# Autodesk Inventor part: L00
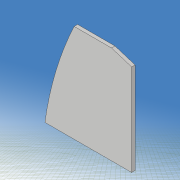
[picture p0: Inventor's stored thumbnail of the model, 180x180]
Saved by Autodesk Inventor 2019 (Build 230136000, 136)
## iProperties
Created: 2021-05
Part Number: L00
Material: 一般
Document SubType Name: Modeling
Designer: kikut
Density: 1 g/cm^3
Appearance: 既定
Mass: 0.00934248 g
Surface Area: 0.426451 cm^2
Volume: 0.00934248 cm^3
Author: kikut
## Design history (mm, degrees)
sketch "スケッチ1"
  geometry: L1 (80, 60)-(-80, 60); L2 (-80, 60)-(-80, -60); L3 (-80, -60)-(80, -60); L4 (80, -60)-(80, 60); L5 (80, 60)-(-80, -60); L6 (-80, 60)-(80, -60); 1 further point
  constraints: 12 end point, 2 midpoint, 2 parallel, 1 horizontal, 1 perpendicular
  dimensions: "d0" = 160 distance of L2.end L3.end; "d1" = 120 distance of L1.end L2.end
extrude "押し出し1" new body sketch "スケッチ1" stored distance "d2" = 0.6; taper "d3" = 0 deg
sketch "スケッチ2"
  geometry: L1 (-140, 0)-(140, 0) reference; L2 (0, -54)-(20, -30); L3 (0, 54)-(20, 30); L4 (0, -3)-(6.514, -3); L5 (6.514, -3)-(16, -6); L6 (16, -6)-(24, -3); L7 (24, -3)-(33.716, -3); L8 (0, 3)-(6.514, 3); L9 (6.514, 3)-(16, 6); L10 (16, 6)-(24, 3); L11 (24, 3)-(33.716, 3); L12 (0, -98)-(0, 98) reference; L13 (-100, -70)-(100, -70); L14 (100, -70)-(100, 70); L15 (100, 70)-(-100, 70); L16 (-100, 70)-(-100, -70); L17 (-100, -70)-(100, 70); L18 (100, -70)-(-100, 70); A1 r 60 centre (54.312, 28.5) between (0, 54) and (0, 3); A2 r 60 centre (54.312, -28.5) between (0, -3) and (0, -54); A3 r 18.111 centre (18, -12) between (20, -30) and (33.716, -3); A4 r 18.111 centre (18, 12) between (33.716, 3) and (20, 30); 1 further point
  constraints: 32 end point, 8 point on circle, 8 symmetric about line, 4 centre point, 3 horizontal, 2 collinear, 2 midpoint, 2 parallel, 1 perpendicular
  dimensions: "d5" = 60 radius of A1; "d6" = 6 distance of L8.start L4.start; "d7" = 108 distance of L3.start L2.start; "d8" = 0 horizontal distance of L3.start L8.start; "d9" = 60 distance of L3.end L2.end; "d10" = 0 horizontal distance of point (0, 0) L3.start; "d11" = 20 horizontal distance of L3.start L3.end; "d12" = 24 distance of A4.centre A3.centre; "d13" = 6 distance of L11.end L7.end; "d14" = 12 distance of L9.end L5.end; "d15" = 16 distance from line of L12 L5.end; "d16" = 24 distance from line of L6.end L12; "d17" = 200 distance of L14.end L15.end; "d18" = 140 distance of L15.end L13.start; "d30" = 18 distance from line of L12 A4.centre
extrude "押し出し2" cut sketch "スケッチ2" stored distance "d19" = 10; taper "d20" = 0 deg
sketch "スケッチ3"
  geometry: L1 (49.705, -17.97)-(33.948, -15.191); L2 (33.948, -15.191)-(34.295, -13.222); L3 (34.295, -13.222)-(50.052, -16); L4 (50.052, -16)-(49.705, -17.97); L5 (49.705, -17.97)-(34.295, -13.222); L6 (33.948, -15.191)-(50.052, -16); L7 (50.052, 16)-(34.295, 13.222); L8 (34.295, 13.222)-(33.948, 15.191); L9 (33.948, 15.191)-(49.705, 17.97); L10 (49.705, 17.97)-(50.052, 16); L11 (50.052, 16)-(33.948, 15.191); L12 (34.295, 13.222)-(49.705, 17.97); L13 (-112, 0)-(112, 0) reference; L14 (0, -84)-(0, 84) reference; 3 further points
  constraints: 24 end point, 4 midpoint, 4 parallel, 2 perpendicular, 2 symmetric about line
  dimensions: "d21" = 2 distance of L3.end L1.start; "d22" = 2 distance of L9.end L7.start; "d23" = 16 distance of L8.end L9.end; "d24" = 42 distance from line of L14 point (42, 15.596); "d26" = 10 deg angle of L7 L13; "d62" = 16 distance from line of L3.end L13
extrude "押し出し3" join sketch "スケッチ3" distance "d27" = 0.6; taper "d28" = 0 deg
fillet "フィレット1" dims "d31" = 2
fillet "フィレット2" dims "d32" = 1
sketch "スケッチ7"
  geometry: L1 (-20, 60)-(80, 60); L2 (80, 60)-(80, -60); L3 (80, -60)-(-20, -60); L4 (-20, -60)-(-20, 60); L5 (0, -82.207)-(0, 85.793) reference; L6 (-40, 0)-(100, 0) reference; L7 (-10, 0)-(10, 0); L8 (10, 0)-(10, -20); L9 (10, -20)-(-10, -20); L10 (-10, -20)-(-10, 0); 1 further point
  constraints: 16 end point, 4 parallel, 2 horizontal, 2 perpendicular, 1 other
  dimensions: "d80" = 120 distance of L3.end L1.start; "d81" = 20 distance between parallel lines of L5 L4; "d82" = 100 distance of L1.start L1.end; "d83" = 0 distance between parallel lines of L7 L6; "d84" = 20 distance of L8.end L9.end; "d85" = 20 distance of L7.end L8.end; "d86" = 10 distance between parallel lines of L4 L10
extrude "押し出し5" cut sketch "スケッチ7" stored distance "d87" = 10; taper "d88" = 0 deg
node "ソリッド1"
